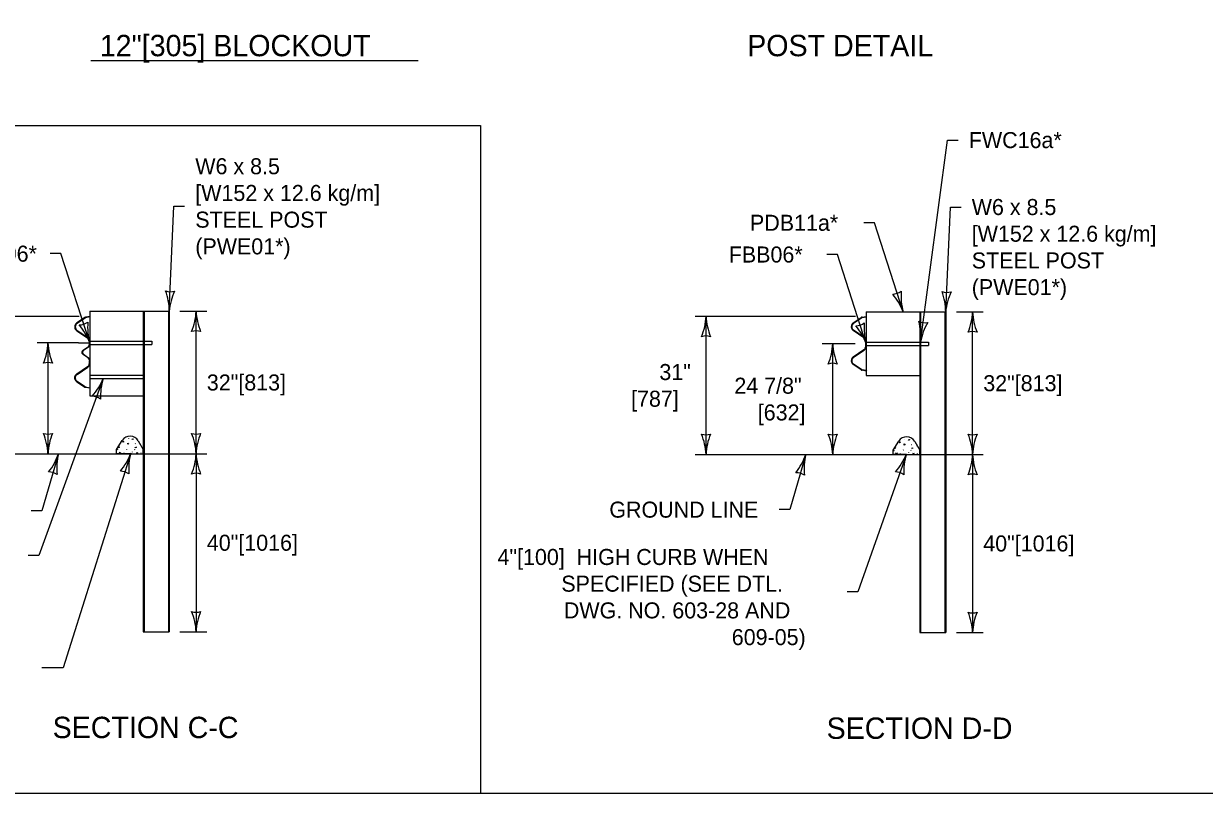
# Model space of a CAD drawing. Extents: x 49991 to 50160, y 49948 to 50051.
# Drawn here: x 50006.556 to 50010.973, y 49987.799 to 49990.681 of the extents above; entities that cross this region are included whole.
import ezdxf

# ---------------------------------------------------------------- set-up
doc = ezdxf.new("R2010")
doc.units = 0
for name, color, linetype in [('Default', 7, 'Continuous'), ('Level 1', 7, 'Continuous'), ('Level 2', 7, 'Continuous'), ('Level 3', 7, 'Continuous'), ('Level 4', 7, 'Continuous')]:
    doc.layers.add(name, color=color, linetype=linetype)

msp = doc.modelspace()

# ---------------------------------------------------------------- linework, layer by layer
at = {"layer": 'Default'}
for p, q in [((50009.6594, 49989.5606), (50009.6892, 49989.5808)), ((50009.6604, 49989.5592), (50009.6902, 49989.5793)), ((50009.6921, 49989.5819), (50009.708, 49989.5848)), ((50009.6924, 49989.5802), (50009.7083, 49989.5831)), ((50009.7083, 49989.5831), (50009.708, 49989.5848)), ((50009.6993, 49989.5047), (50009.6594, 49989.5316)), ((50009.7002, 49989.5062), (50009.6604, 49989.5331)), ((50009.6746, 49989.5235), (50009.6733, 49989.5223)), ((50006.8034, 49989.4786), (50006.8034, 49989.4786)), ((50009.7062, 49989.4733), (50009.7062, 49989.4917)), ((50009.708, 49989.4733), (50009.708, 49989.4917)), ((50006.7776, 49989.4548), (50006.7797, 49989.457)), ((50009.6594, 49989.4333), (50009.6993, 49989.4602)), ((50009.6604, 49989.4319), (50009.7002, 49989.4588)), ((50006.8034, 49989.4065), (50006.8034, 49989.4069)), ((50009.6892, 49989.3842), (50009.6594, 49989.4043)), ((50009.6902, 49989.3856), (50009.6604, 49989.4058)), ((50009.6689, 49989.4), (50009.6677, 49989.3988)), ((50009.708, 49989.3801), (50009.6921, 49989.383)), ((50009.7083, 49989.3818), (50009.6924, 49989.3848)), ((50009.7083, 49989.3818), (50009.708, 49989.3801)), ((50006.7836, 49989.3226), (50006.7826, 49989.324)), ((50006.8034, 49989.3158), (50006.8038, 49989.3175))]:
    msp.add_line(p, q, dxfattribs=at)
for centre, radius, start, end in [((50009.6934, 49989.5746), 0.00744, 100.4285, 124.048), ((50009.6934, 49989.5746), 0.00569, 100.4285, 124.048), ((50009.6692, 49989.5461), 0.0175, 124.048, 235.952), ((50009.6692, 49989.5461), 0.0157, 124.048, 235.952), ((50009.6905, 49989.4917), 0.0157, 0, 55.952), ((50009.6905, 49989.4917), 0.0175, 0, 55.952), ((50009.6692, 49989.4188), 0.0175, 124.048, 235.952), ((50009.6692, 49989.4188), 0.0157, 124.048, 235.952), ((50009.6905, 49989.4733), 0.0157, 304.048, 0), ((50009.6905, 49989.4733), 0.0175, 304.048, 0), ((50009.6934, 49989.3904), 0.00744, 235.952, 259.5715), ((50009.6934, 49989.3904), 0.00569, 235.952, 259.5715)]:
    msp.add_arc(centre, radius, start, end, dxfattribs=at)
at = {"layer": 'Level 1'}
for p, q in [((49999.3835, 49990.2991), (50008.2653, 49990.2991)), ((50008.2653, 49990.2991), (50008.2653, 49987.7988)), ((50006.7847, 49989.5801), (50006.7549, 49989.56)), ((50006.7857, 49989.5786), (50006.7559, 49989.5585)), ((50006.7705, 49989.5684), (50006.7695, 49989.5698)), ((50006.7836, 49989.5772), (50006.7826, 49989.5786)), ((50006.8034, 49989.5842), (50006.7876, 49989.5813)), ((50006.8038, 49989.5825), (50006.7879, 49989.5795)), ((50006.8034, 49989.5842), (50006.8013, 49989.582)), ((50006.8034, 49989.6039), (50006.8034, 49989.2873)), ((50006.8034, 49989.6039), (50007.0034, 49989.6039)), ((50006.8038, 49989.5825), (50006.8034, 49989.5842)), ((50007.0034, 49989.6039), (50007.0034, 49989.2873)), ((50007.0034, 49989.6039), (50007.0034, 49988.4039)), ((50007.0034, 49989.6039), (50007.1006, 49989.6039)), ((50007.0067, 49989.6039), (50007.0067, 49988.4039)), ((50007.0974, 49989.6039), (50007.0974, 49988.4039)), ((50007.1006, 49989.6039), (50007.1006, 49988.4039)), ((50009.6594, 49989.5606), (50009.6892, 49989.5808)), ((50009.6604, 49989.5592), (50009.6902, 49989.5793)), ((50009.6921, 49989.5819), (50009.708, 49989.5848)), ((50009.6924, 49989.5802), (50009.7083, 49989.5831)), ((50009.708, 49989.6012), (50009.708, 49989.3637)), ((50009.708, 49989.6012), (50009.908, 49989.6012)), ((50009.7083, 49989.5831), (50009.708, 49989.5848)), ((50009.908, 49989.6012), (50009.908, 49989.3637)), ((50009.908, 49989.6012), (50009.908, 49988.4012)), ((50009.908, 49989.6012), (50010.0051, 49989.6012)), ((50009.9112, 49989.6012), (50009.9112, 49988.4012)), ((50010.0019, 49989.6012), (50010.0019, 49988.4012)), ((50010.0051, 49989.6012), (50010.0051, 49988.4012)), ((50006.7536, 49989.5343), (50006.7524, 49989.5331)), ((50006.7549, 49989.531), (50006.7948, 49989.504)), ((50006.7559, 49989.5324), (50006.7957, 49989.5055)), ((50006.7705, 49989.5226), (50006.7695, 49989.5211)), ((50009.6993, 49989.5047), (50009.6594, 49989.5316)), ((50009.7002, 49989.5062), (50009.6604, 49989.5331)), ((50009.6746, 49989.5235), (50009.6733, 49989.5223)), ((50006.7836, 49989.5137), (50006.7826, 49989.5123)), ((50006.7886, 49989.5104), (50006.7873, 49989.5091)), ((50006.8017, 49989.4917), (50006.8034, 49989.4917)), ((50006.8017, 49989.4793), (50006.8017, 49989.491)), ((50006.8034, 49989.4884), (50006.8017, 49989.4884)), ((50006.8034, 49989.4786), (50006.8017, 49989.4786)), ((50006.8034, 49989.4793), (50006.8034, 49989.491)), ((50007.0067, 49989.4914), (50007.0357, 49989.4914)), ((50007.0067, 49989.4789), (50007.0357, 49989.4789)), ((50007.0357, 49989.4914), (50007.0357, 49989.4789)), ((50009.7062, 49989.4733), (50009.7062, 49989.4917)), ((50009.708, 49989.4733), (50009.708, 49989.4917)), ((50009.9112, 49989.4887), (50009.9402, 49989.4887)), ((50009.9112, 49989.4762), (50009.9402, 49989.4762)), ((50009.9402, 49989.4887), (50009.9402, 49989.4762)), ((50006.7783, 49989.4577), (50006.7982, 49989.4721)), ((50006.7982, 49989.4279), (50006.7783, 49989.4423)), ((50006.7996, 49989.4713), (50006.7797, 49989.457)), ((50006.7797, 49989.443), (50006.7996, 49989.4286)), ((50009.6594, 49989.4333), (50009.6993, 49989.4602)), ((50009.6604, 49989.4319), (50009.7002, 49989.4588)), ((50006.7948, 49989.3959), (50006.7549, 49989.369)), ((50006.7559, 49989.3676), (50006.7957, 49989.3945)), ((50006.8025, 49989.4065), (50006.8011, 49989.405)), ((50006.8033, 49989.4065), (50006.8015, 49989.4065)), ((50006.8017, 49989.4205), (50006.8017, 49989.4196)), ((50006.8017, 49989.4196), (50006.8034, 49989.4196)), ((50006.8017, 49989.4069), (50006.8017, 49989.4185)), ((50006.8017, 49989.4069), (50006.8017, 49989.4065)), ((50006.8033, 49989.4065), (50006.8034, 49989.4065)), ((50006.8034, 49989.4205), (50006.8034, 49989.4196)), ((50006.8034, 49989.4069), (50006.8034, 49989.4185)), ((50009.6892, 49989.3842), (50009.6594, 49989.4043)), ((50009.6902, 49989.3856), (50009.6604, 49989.4058)), ((50009.6689, 49989.4), (50009.6677, 49989.3988)), ((50006.7492, 49989.3531), (50006.7475, 49989.3515)), ((50009.708, 49989.3801), (50009.6921, 49989.383)), ((50009.7083, 49989.3818), (50009.6924, 49989.3848)), ((50009.7083, 49989.3818), (50009.708, 49989.3801)), ((50009.708, 49989.3637), (50009.908, 49989.3637)), ((50006.7549, 49989.34), (50006.7847, 49989.3199)), ((50006.7857, 49989.3213), (50006.7559, 49989.3415)), ((50006.7801, 49989.3251), (50006.7788, 49989.3239)), ((50006.8034, 49989.3158), (50006.7876, 49989.3187)), ((50006.7879, 49989.3205), (50006.8038, 49989.3175)), ((50006.8034, 49989.2873), (50007.0034, 49989.2873)), ((50006.9477, 49989.127), (50006.9482, 49989.1262)), ((50009.8522, 49989.1243), (50009.8527, 49989.1235)), ((50006.9035, 49989.0866), (50006.9248, 49989.1206)), ((50006.9035, 49989.0726), (50006.9035, 49989.0866)), ((50006.9066, 49989.0862), (50006.9071, 49989.0854)), ((50006.9071, 49989.0859), (50006.9077, 49989.0851)), ((50006.9418, 49989.0862), (50006.9424, 49989.0874)), ((50006.9705, 49989.0862), (50006.971, 49989.0854)), ((50006.971, 49989.0859), (50006.9716, 49989.0851)), ((50006.9733, 49989.1072), (50006.9738, 49989.1084)), ((50006.9736, 49989.0931), (50006.9748, 49989.0957)), ((50006.9846, 49989.1189), (50007.0034, 49989.0866)), ((50006.9936, 49989.1017), (50006.9941, 49989.1027)), ((50007.0034, 49989.0706), (50007.0034, 49989.0866)), ((50009.808, 49989.0839), (50009.8293, 49989.1179)), ((50009.808, 49989.0699), (50009.808, 49989.0839)), ((50009.8111, 49989.0835), (50009.8116, 49989.0827)), ((50009.8116, 49989.0832), (50009.8122, 49989.0824)), ((50009.8463, 49989.0835), (50009.8469, 49989.0847)), ((50009.875, 49989.0835), (50009.8755, 49989.0827)), ((50009.8755, 49989.0832), (50009.8761, 49989.0824)), ((50009.8778, 49989.1045), (50009.8783, 49989.1057)), ((50009.8781, 49989.0904), (50009.8793, 49989.093)), ((50009.8891, 49989.1162), (50009.908, 49989.0839)), ((50009.8981, 49989.099), (50009.8986, 49989.1)), ((50009.908, 49989.0679), (50009.908, 49989.0839)), ((50006.9035, 49989.0726), (50007.0034, 49989.0706)), ((50006.931, 49989.0733), (50006.9315, 49989.0745)), ((50006.9535, 49989.0716), (50006.9535, 49989.0716)), ((50006.9535, 49989.0716), (50006.9535, 49989.0716)), ((50006.9626, 49989.0763), (50006.9632, 49989.0775)), ((50006.9949, 49989.0733), (50006.9955, 49989.0745)), ((50009.808, 49989.0699), (50009.908, 49989.0679)), ((50009.8355, 49989.0706), (50009.8361, 49989.0718)), ((50009.858, 49989.0689), (50009.858, 49989.0689)), ((50009.858, 49989.0689), (50009.858, 49989.0689)), ((50009.8671, 49989.0736), (50009.8677, 49989.0748)), ((50009.8994, 49989.0706), (50009.9, 49989.0718)), ((50007.0034, 49988.4039), (50007.1006, 49988.4039)), ((50009.908, 49988.4012), (50010.0051, 49988.4012))]:
    msp.add_line(p, q, dxfattribs=at)
msp.add_lwpolyline([(49999.3835, 49998.9992), (50016.7501, 49998.9992), (50016.7501, 49987.7988), (49999.3835, 49987.7988)], close=True, dxfattribs=at)
for points in [[(50006.7982, 49989.4721), (50006.7994, 49989.4732), (50006.8003, 49989.4745), (50006.801, 49989.4759), (50006.8015, 49989.4774), (50006.8016, 49989.4785), (50006.8017, 49989.4786)], [(50006.8034, 49989.4786), (50006.8033, 49989.4775), (50006.8027, 49989.4756), (50006.8019, 49989.474), (50006.8008, 49989.4725), (50006.8002, 49989.4719), (50006.7996, 49989.4713)], [(50006.8017, 49989.491), (50006.8017, 49989.4917), (50006.8017, 49989.4917)], [(50006.8017, 49989.4793), (50006.8017, 49989.4787), (50006.8017, 49989.4786)], [(50006.8034, 49989.491), (50006.8034, 49989.4917), (50006.8034, 49989.4917)], [(50006.8034, 49989.4786), (50006.8034, 49989.479), (50006.8034, 49989.4793)], [(50006.7783, 49989.4423), (50006.777, 49989.4435), (50006.7759, 49989.4449), (50006.7752, 49989.4464), (50006.7747, 49989.4479), (50006.7745, 49989.4495), (50006.7745, 49989.4512), (50006.7749, 49989.4528), (50006.7755, 49989.4543), (50006.7763, 49989.4557), (50006.7774, 49989.4569), (50006.7783, 49989.4577)], [(50006.7797, 49989.457), (50006.7791, 49989.4565), (50006.7785, 49989.4559), (50006.778, 49989.4553), (50006.7775, 49989.4545), (50006.7771, 49989.4537), (50006.7768, 49989.4531), (50006.7766, 49989.4525), (50006.7764, 49989.4518), (50006.7763, 49989.4509), (50006.7762, 49989.4502), (50006.7762, 49989.4496), (50006.7763, 49989.4488), (50006.7765, 49989.4476), (50006.7768, 49989.4467), (50006.7772, 49989.446), (50006.7776, 49989.4452), (50006.778, 49989.4446), (50006.7784, 49989.4442), (50006.7789, 49989.4437), (50006.7797, 49989.443)], [(50006.7948, 49989.3959), (50006.7963, 49989.3971), (50006.7977, 49989.3985), (50006.7992, 49989.4006), (50006.8005, 49989.4029), (50006.8015, 49989.4065)], [(50006.8033, 49989.4065), (50006.8029, 49989.4047), (50006.802, 49989.4019), (50006.8006, 49989.3993), (50006.7987, 49989.397), (50006.7965, 49989.3951), (50006.7957, 49989.3945)], [(50006.8017, 49989.4205), (50006.8015, 49989.4223), (50006.801, 49989.4242), (50006.8002, 49989.4256), (50006.7992, 49989.4269), (50006.7987, 49989.4274), (50006.7982, 49989.4279)], [(50006.7996, 49989.4286), (50006.801, 49989.4272), (50006.8022, 49989.4255), (50006.8029, 49989.4239), (50006.8033, 49989.4222), (50006.8034, 49989.4213), (50006.8034, 49989.4205)], [(50006.8017, 49989.4196), (50006.8017, 49989.4192), (50006.8017, 49989.4185)], [(50006.8034, 49989.4185), (50006.8034, 49989.4194), (50006.8034, 49989.4196)], [(50006.7549, 49989.34), (50006.7538, 49989.3409), (50006.7527, 49989.3418), (50006.7517, 49989.3429), (50006.7507, 49989.3441), (50006.7493, 49989.3462), (50006.7486, 49989.3478), (50006.748, 49989.3493), (50006.7474, 49989.3518), (50006.7473, 49989.3536), (50006.7472, 49989.3551), (50006.7475, 49989.3577), (50006.7479, 49989.3594), (50006.7484, 49989.3609), (50006.7492, 49989.3625), (50006.7499, 49989.3638), (50006.7505, 49989.3647), (50006.7515, 49989.3659), (50006.7524, 49989.367), (50006.7533, 49989.3678), (50006.7549, 49989.369)], [(50006.7559, 49989.3676), (50006.7539, 49989.3659), (50006.7521, 49989.3639), (50006.7507, 49989.3617), (50006.7497, 49989.3592), (50006.7491, 49989.3566), (50006.749, 49989.354), (50006.7493, 49989.3513), (50006.7501, 49989.3488), (50006.7512, 49989.3464), (50006.7528, 49989.3443), (50006.7543, 49989.3428), (50006.7559, 49989.3415)], [(50006.9617, 49989.1236), (50006.9633, 49989.1269), (50006.966, 49989.1249), (50006.9617, 49989.1236)], [(50009.8662, 49989.1209), (50009.8678, 49989.1242), (50009.8705, 49989.1222), (50009.8662, 49989.1209)], [(50006.9097, 49989.0931), (50006.9113, 49989.0965), (50006.9139, 49989.0945), (50006.9097, 49989.0931)], [(50006.927, 49989.114), (50006.9286, 49989.1174), (50006.9313, 49989.1154), (50006.927, 49989.114)], [(50006.9451, 49989.1059), (50006.9456, 49989.1097), (50006.9493, 49989.1059)], [(50006.9763, 49989.0957), (50006.9778, 49989.0945), (50006.9736, 49989.0931)], [(50009.8142, 49989.0904), (50009.8158, 49989.0938), (50009.8184, 49989.0918), (50009.8142, 49989.0904)], [(50009.8315, 49989.1113), (50009.8331, 49989.1147), (50009.8358, 49989.1127), (50009.8315, 49989.1113)], [(50009.8496, 49989.1032), (50009.8501, 49989.107), (50009.8538, 49989.1032)], [(50009.8808, 49989.093), (50009.8823, 49989.0918), (50009.8781, 49989.0904)], [(50006.9145, 49989.0724), (50006.9166, 49989.0765), (50006.9185, 49989.0723)], [(50006.9777, 49989.0711), (50006.9805, 49989.0765), (50006.9829, 49989.071)], [(50009.819, 49989.0697), (50009.8211, 49989.0738), (50009.823, 49989.0696)], [(50009.8822, 49989.0684), (50009.885, 49989.0738), (50009.8874, 49989.0683)]]:
    msp.add_lwpolyline(points, dxfattribs=at)
for centre, radius, start, end in [((50006.7889, 49989.5739), 0.00744, 100.4285, 124.048), ((50006.7889, 49989.5739), 0.00569, 100.4285, 124.048), ((50009.6934, 49989.5746), 0.00744, 100.4285, 124.048), ((50009.6934, 49989.5746), 0.00569, 100.4285, 124.048), ((50006.7647, 49989.5455), 0.0175, 124.048, 235.952), ((50006.7647, 49989.5455), 0.0157, 124.048, 235.952), ((50009.6692, 49989.5461), 0.0175, 124.048, 235.952), ((50009.6692, 49989.5461), 0.0157, 124.048, 235.952), ((50006.7859, 49989.491), 0.0157, 2.6292, 55.952), ((50006.7859, 49989.491), 0.0175, 2.3659, 55.952), ((50009.6905, 49989.4917), 0.0157, 0, 55.952), ((50009.6905, 49989.4917), 0.0175, 0, 55.952), ((50009.6692, 49989.4188), 0.0175, 124.048, 235.952), ((50009.6692, 49989.4188), 0.0157, 124.048, 235.952), ((50009.6905, 49989.4733), 0.0157, 304.048, 0), ((50009.6905, 49989.4733), 0.0175, 304.048, 0), ((50009.6934, 49989.3904), 0.00744, 235.952, 259.5715), ((50009.6934, 49989.3904), 0.00569, 235.952, 259.5715), ((50006.7889, 49989.326), 0.00744, 235.9564, 259.5671), ((50006.7889, 49989.326), 0.00569, 235.9564, 259.5671), ((50006.9542, 49989.1012), 0.0352, 30.1855, 146.6195), ((50009.8587, 49989.0985), 0.0352, 30.1855, 146.6195)]:
    msp.add_arc(centre, radius, start, end, dxfattribs=at)
at = {"layer": 'Level 2'}
msp.add_line((50006.8069, 49990.5427), (50008.0315, 49990.5427), dxfattribs=at)
at = {"layer": 'Level 3'}
for p, q in [((50009.9112, 49989.4887), (50010.0115, 49990.2447)), ((50010.0115, 49990.2447), (50010.0515, 49990.2447)), ((50007.1006, 49989.6039), (50007.118, 49989.9969)), ((50007.118, 49989.9969), (50007.158, 49989.9969)), ((50010.0051, 49989.6012), (50010.0225, 49989.9942)), ((50010.0225, 49989.9942), (50010.0625, 49989.9942)), ((50009.7383, 49989.9352), (50009.6983, 49989.9352)), ((50009.8461, 49989.6012), (50009.7383, 49989.9352)), ((50006.6956, 49989.8196), (50006.6556, 49989.8196)), ((50006.8034, 49989.4857), (50006.6956, 49989.8196)), ((50009.6001, 49989.8164), (50009.5601, 49989.8164)), ((50009.708, 49989.4825), (50009.6001, 49989.8164)), ((50006.7634, 49989.5842), (50006.1288, 49989.5842)), ((50007.1406, 49989.6039), (50007.2412, 49989.6039)), ((50007.2012, 49989.0706), (50007.2012, 49989.6039)), ((50009.668, 49989.5848), (50009.0685, 49989.5848)), ((50009.1085, 49989.0679), (50009.1085, 49989.5848)), ((50010.0451, 49989.6012), (50010.1457, 49989.6012)), ((50010.1057, 49989.0679), (50010.1057, 49989.6012)), ((50006.7617, 49989.4851), (50006.607, 49989.4851)), ((50006.647, 49989.4851), (50006.647, 49989.0706)), ((50006.7617, 49989.4851), (50006.8017, 49989.4851)), ((50009.6662, 49989.4825), (50009.5425, 49989.4825)), ((50009.5825, 49989.0679), (50009.5825, 49989.4825)), ((50006.8536, 49989.3519), (50006.6125, 49988.6898)), ((50006.1288, 49989.0706), (50007.2412, 49989.0706)), ((50006.6864, 49989.0706), (50006.6245, 49988.8563)), ((50006.9565, 49989.0726), (50006.7041, 49988.2686)), ((50007.2012, 49989.0706), (50007.2012, 49988.4039)), ((50009.0685, 49989.0679), (50010.1457, 49989.0679)), ((50009.4817, 49989.0679), (50009.422, 49988.8612)), ((50009.858, 49989.0689), (50009.6761, 49988.554)), ((50010.1057, 49989.0679), (50010.1057, 49988.4012)), ((50009.422, 49988.8612), (50009.382, 49988.8612)), ((50006.6245, 49988.8563), (50006.5845, 49988.8563)), ((50006.6125, 49988.6898), (50006.5725, 49988.6898)), ((50009.6761, 49988.554), (50009.6361, 49988.554)), ((50007.1406, 49988.4039), (50007.2412, 49988.4039)), ((50010.0451, 49988.4012), (50010.1457, 49988.4012)), ((50006.6641, 49988.2686), (50006.6241, 49988.2686)), ((50006.7041, 49988.2686), (50006.6641, 49988.2686))]:
    msp.add_line(p, q, dxfattribs=at)
for centre, radius, start, end in [((50007.1063, 49989.732), 0.0548, 249.601, 285.3234), ((50006.8676, 49989.6028), 0.233, 0.2895, 19.5394), ((50007.3221, 49989.5849), 0.2223, 154.9182, 175.1017), ((50009.8067, 49989.7232), 0.0548, 270.0345, 305.7569), ((50009.6282, 49989.5188), 0.233, 20.723, 39.9729), ((50010.0603, 49989.6608), 0.2223, 175.3517, 195.5352), ((50010.0108, 49989.7293), 0.0548, 249.601, 285.3234), ((50009.7721, 49989.6001), 0.233, 0.2895, 19.5394), ((50010.2266, 49989.5822), 0.2223, 154.9182, 175.1017), ((50006.9791, 49989.6131), 0.2223, 337.456, 357.6395), ((50007.4339, 49989.6154), 0.233, 182.8273, 202.0772), ((50008.8864, 49989.594), 0.2223, 337.456, 357.6395), ((50009.3412, 49989.5963), 0.233, 182.8273, 202.0772), ((50009.928, 49989.6158), 0.0548, 244.5798, 280.3022), ((50009.679, 49989.508), 0.233, 355.2683, 14.5181), ((50009.8836, 49989.6104), 0.2223, 337.456, 357.6395), ((50010.3384, 49989.6127), 0.233, 182.8273, 202.0772), ((50006.764, 49989.6077), 0.0548, 270.0345, 305.7569), ((50006.5855, 49989.4032), 0.233, 20.723, 39.9729), ((50007.0176, 49989.5452), 0.2223, 175.3517, 195.5352), ((50007.2012, 49989.4757), 0.0548, 72.1388, 107.8612), ((50009.6686, 49989.6045), 0.0548, 270.0345, 305.7569), ((50009.49, 49989.4), 0.233, 20.723, 39.9729), ((50009.9221, 49989.542), 0.2223, 175.3517, 195.5352), ((50010.1302, 49989.4504), 0.2223, 149.897, 170.0805), ((50010.1057, 49989.473), 0.0548, 72.1388, 107.8612), ((50006.4249, 49989.4943), 0.2223, 337.456, 357.6395), ((50006.8797, 49989.4966), 0.233, 182.8273, 202.0772), ((50009.1085, 49989.4566), 0.0548, 72.1388, 107.8612), ((50009.3604, 49989.4916), 0.2223, 337.456, 357.6395), ((50009.8152, 49989.494), 0.233, 182.8273, 202.0772), ((50006.647, 49989.3569), 0.0548, 72.1388, 107.8612), ((50009.5825, 49989.3543), 0.0548, 72.1388, 107.8612), ((50006.6481, 49989.4365), 0.2223, 317.441, 337.6245), ((50007.0762, 49989.283), 0.233, 162.8123, 182.0622), ((50006.8098, 49989.2314), 0.0548, 52.1238, 87.8462), ((50006.647, 49989.1988), 0.0548, 252.1388, 287.8612), ((50006.4143, 49989.0591), 0.233, 2.8273, 22.0772), ((50006.8692, 49989.0614), 0.2223, 157.456, 177.6395), ((50007.2012, 49989.1988), 0.0548, 252.1388, 287.8612), ((50006.9685, 49989.0591), 0.233, 2.8273, 22.0772), ((50007.4233, 49989.0614), 0.2223, 157.456, 177.6395), ((50009.1085, 49989.1961), 0.0548, 252.1388, 287.8612), ((50008.8758, 49989.0564), 0.233, 2.8273, 22.0772), ((50009.3306, 49989.0587), 0.2223, 157.456, 177.6395), ((50009.5825, 49989.1961), 0.0548, 252.1388, 287.8612), ((50009.3498, 49989.0564), 0.233, 2.8273, 22.0772), ((50009.8046, 49989.0587), 0.2223, 157.456, 177.6395), ((50010.1057, 49989.1961), 0.0548, 252.1388, 287.8612), ((50009.873, 49989.0564), 0.233, 2.8273, 22.0772), ((50010.3278, 49989.0587), 0.2223, 157.456, 177.6395), ((50006.4756, 49989.1411), 0.2223, 321.3407, 341.5242), ((50006.9132, 49989.017), 0.233, 166.712, 185.9619), ((50006.7473, 49989.1478), 0.2223, 320.03, 340.2135), ((50007.182, 49989.0139), 0.233, 165.4013, 184.6512), ((50006.9791, 49989.0797), 0.2223, 337.456, 357.6395), ((50007.4339, 49989.0821), 0.233, 182.8273, 202.0772), ((50009.2708, 49989.1383), 0.2223, 321.3407, 341.5242), ((50009.7085, 49989.0143), 0.233, 166.712, 185.9619), ((50009.6516, 49989.1515), 0.2223, 318.0037, 338.1872), ((50010.0812, 49989.0022), 0.233, 163.375, 182.6248), ((50009.8836, 49989.077), 0.2223, 337.456, 357.6395), ((50010.3384, 49989.0794), 0.233, 182.8273, 202.0772), ((50006.6508, 49988.9474), 0.0548, 56.0235, 91.7459), ((50006.9181, 49988.9502), 0.0548, 54.7128, 90.4352), ((50007.2012, 49988.9424), 0.0548, 72.1388, 107.8612), ((50009.4461, 49988.9447), 0.0548, 56.0235, 91.7459), ((50009.8153, 49988.948), 0.0548, 52.6865, 88.4089), ((50010.1057, 49988.9397), 0.0548, 72.1388, 107.8612), ((50007.2012, 49988.5321), 0.0548, 252.1388, 287.8612), ((50006.9685, 49988.3924), 0.233, 2.8273, 22.0772), ((50007.4233, 49988.3948), 0.2223, 157.456, 177.6395), ((50010.1057, 49988.5294), 0.0548, 252.1388, 287.8612), ((50009.873, 49988.3897), 0.233, 2.8273, 22.0772), ((50010.3278, 49988.3921), 0.2223, 157.456, 177.6395)]:
    msp.add_arc(centre, radius, start, end, dxfattribs=at)
at = {"layer": 'Level 4'}
for p, q in [((50006.8034, 49989.4914), (50007.0067, 49989.4914)), ((50006.8034, 49989.4789), (50007.0067, 49989.4789)), ((50009.708, 49989.4887), (50009.9112, 49989.4887)), ((50009.708, 49989.4762), (50009.9112, 49989.4762)), ((50006.8034, 49989.3644), (50007.0067, 49989.3644)), ((50006.8034, 49989.3519), (50007.0067, 49989.3519))]:
    msp.add_line(p, q, dxfattribs=at)

# ---------------------------------------------------------------- texts
at = {"layer": 'Level 2'}
for s, height, p in [('12"[305] BLOCKOUT', 0.08, (50006.8408, 49990.5587)), ('POST DETAIL', 0.08, (50009.2626, 49990.5587)), ('FWC16a*', 0.06, (50010.0915, 49990.2147)), ('W6 x 8.5', 0.06, (50007.198, 49990.1169)), ('[W152 x 12.6 kg/m]', 0.06, (50007.198, 49990.0169)), ('W6 x 8.5', 0.06, (50010.1025, 49989.9642)), ('STEEL POST', 0.06, (50007.198, 49989.9169)), ('PDB11a*', 0.06, (50009.2729, 49989.9052)), ('[W152 x 12.6 kg/m]', 0.06, (50010.1025, 49989.8642)), ('(PWE01*)', 0.06, (50007.198, 49989.8169)), ('FBB06*', 0.06, (50006.3291, 49989.7896)), ('FBB06*', 0.06, (50009.1936, 49989.7864)), ('STEEL POST', 0.06, (50010.1025, 49989.7642)), ('(PWE01*)', 0.06, (50010.1025, 49989.6642)), ('31"', 0.06, (50008.934, 49989.3464)), ('32"[813]', 0.06, (50007.2412, 49989.3073)), ('24 7/8"', 0.06, (50009.2145, 49989.2952)), ('32"[813]', 0.06, (50010.1457, 49989.3046)), ('[787]', 0.06, (50008.8281, 49989.2464)), ('[632]', 0.06, (50009.3021, 49989.1952)), ('GROUND LINE', 0.06, (50008.7468, 49988.8312)), ('40"[1016]', 0.06, (50007.2412, 49988.7073)), ('40"[1016]', 0.06, (50010.1457, 49988.7046)), ('4"[100]  HIGH CURB WHEN ', 0.06, (50008.3286, 49988.654)), ('SPECIFIED (SEE DTL. ', 0.06, (50008.5673, 49988.554)), ('DWG. NO. 603-28 AND ', 0.06, (50008.5768, 49988.454)), ('609-05) ', 0.06, (50009.2049, 49988.354)), ('SECTION C-C', 0.08, (50006.6643, 49988.0058)), ('SECTION D-D', 0.08, (50009.5596, 49988.003))]:
    msp.add_text(s, height=height, dxfattribs=at).set_placement(p)

doc.saveas('drawing.dxf')
